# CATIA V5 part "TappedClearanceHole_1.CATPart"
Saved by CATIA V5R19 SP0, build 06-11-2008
Bounding box of the stored display mesh (mm): x -15.45 to 8.962, y -8.71 to 14.473, z -25.999 to 10.969
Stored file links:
  D:\D6\Data\SampleData\GeneralData\Catalog\Udfs\TappedClearanceHole_1.CATPart
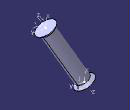
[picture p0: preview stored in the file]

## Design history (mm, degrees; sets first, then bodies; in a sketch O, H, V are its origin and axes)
AxisSystem1 "MainAxisSystem": origin (3.4402, -3.0557, 7.9698), X (-0.7522, -0.6549, 0.0736), Y (0.5427, -0.6789, -0.4946), Z (0.3738, -0.332, 0.866)
Intersect1 "Intersect": ToIntersect1 edge [ZX plane of AxisSystem1 | YZ plane of AxisSystem1], ToIntersect2 Plane2
Project1 "Project": Support Plane2, ToProject vertex [YZ plane of AxisSystem1 | ZX plane of AxisSystem1 | XY plane of AxisSystem1]
Body1 (main body)
  Point1: type OnPlane, Support xy-plane, Direction (1, 0, 0), H -42, V -75
  Point2: type OnPlane, Support xy-plane, Direction (1, 0, 0), H 109, V 95
  Line1: type PtPt, SecondPoint Point2, FirstPoint Point1
  Plane1 "InsertionDirection": type Angle, Angle 30, Direction Line1, RefPlane xy-plane
  Point3 "InsertionPoint": type OnPlane, Support Plane1, Direction (1, 0, 0), H 0, V 0
  Plane2 "LimitingSketchAxis": type Offset, Offset 20, RefPlane xy-plane, reversed
  Body2 "UDF_Body"
    Sketch1 "MainProfileSketch" on ZX plane of AxisSystem1, origin (3.4402, -3.0557, 7.9698), H (0.7522, 0.6549, -0.0736), V (0.3738, -0.332, 0.866)
      axis line L1 (0, 0) -> (0, -35.7608)
      point P2 (4.25, -34.0108)
      line L2 (4.25, -34.0108) -> (4.25, -1.75)
      line L3 (4.25, -1.75) -> (6, 0)
      point P3 (6, 0)
      line L4 (6, 0) -> (6, 0)
      line L5 (6, 0) -> (6, 0)
      line L6 (6, 0) -> (0, 0)
      construction line L7 (6, 0) -> (0, 0)
      reference projected line E1 through (0, 0) direction (-1, 0) from edge [XY plane of AxisSystem1 | ZX plane of AxisSystem1]
      reference projected line E2 through (0, 0) direction (-1, 0) from edge [XY plane of AxisSystem1 | ZX plane of AxisSystem1]
      reference projected line E3 through (0, 0) direction (-1, 0) from edge [XY plane of AxisSystem1 | ZX plane of AxisSystem1]
      reference projected line E4 through (0, 0) direction (0, 1) from edge [ZX plane of AxisSystem1 | YZ plane of AxisSystem1]
      line L8 (4.25, -34.0108) -> (6, -35.7608)
      point P6 (6, -35.7608)
      line L9 (6, -35.7608) -> (0, -35.7608)
      point P8 (-6, -35.7608)
      point P9 (-4.25, -34.0108)
      construction line L10 (-4.25, -34.0108) -> (-6, -35.7608)
      point P10 (4.25, -1.75)
      point P11 (-6, 0)
      point P12 (-4.25, -1.75)
      construction line L11 (-4.25, -1.75) -> (-6, 0)
      angle L3 L11 = 90
      "Radius" L1 L2 = 4.25 {= Body2.DK / 2}
      distance E1 L9 = 35.7608 {= Body2.Offset + (Sketch1.length(L9) * (Body2.Offset / Body2.Offset ))}
      length L7 = 6 {= sqrt((Body2.AS_H * Body2.AS_H ) + ((Groove1.top_width / 2 + Groove1.AS_ZR ) * (Groove1.top_width / 2 + Groove1.AS_ZR )))}
      angle L7 L4 = 0 {= atan(Body2.AS_H / (Groove1.top_width / 2 + Groove1.AS_ZR ))}
      angle L8 L10 = 90
      length L9 = 6 (reference)
      "Radius" P3 L1 = 6 {= Body2.DF1 / 2}
      "Radius" P6 L1 = 6 {= Body2.DF2 / 2}
      coincidence: E2 L4, L1 E4
      perpendicularity: L1 L6, E3 L5
      symmetry: P6 P8 L1, P2 P9 L1, L8 L10 L1, P3 P11 L1, P10 P12 L1, L3 L11 L1
    Groove1 "MainGroove": profile Sketch1, axis Sketch1.L1, angle 360
    Thread1 "Tap": diameter 10, depth 30, pitch 1.5, on face of Groove1 from Sketch1.L2, from {plane type Normal, Curve edge [ZX plane of AxisSystem1 | YZ plane of AxisSystem1], RefPoint vertex [YZ plane of AxisSystem1 | ZX plane of AxisSystem1 | XY plane of AxisSystem1]}
    Point4 "LimitingAxisSystemOrigin": type OnCurve, Support edge [ZX plane of AxisSystem1 | YZ plane of AxisSystem1], Length 3.4641 {= (Sketch1.length(L9)) * (Body2.Offset / Body2.Offset)}, RefPoint Intersect1
    AxisSystem2 "LimitingAxisSystem": origin (-9.9281, 8.8185, -23), X (-0.7522, -0.6549, 0.0736), Y (0.5427, -0.6789, -0.4946), Z (-0.3738, 0.332, -0.866)
  Assemble1 "UDF_Assemble": tool Body2
Body3 "UDF_Body"
  AxisSystem3 "MainAxisSystem": origin (3.4402, -3.0557, 7.9698), X (-0.7522, -0.6549, 0.0736), Y (0.5427, -0.6789, -0.4946), Z (0.3738, -0.332, 0.866)
  Project2 "Project": Support Plane2, ToProject vertex [YZ plane of AxisSystem3 | ZX plane of AxisSystem3 | XY plane of AxisSystem3]
  Intersect2 "Intersect": ToIntersect1 edge [ZX plane of AxisSystem3 | YZ plane of AxisSystem3], ToIntersect2 Plane2
  Sketch2 "MainProfileSketch" on ZX plane of AxisSystem3, origin (3.4402, -3.0557, 7.9698), H (0.7522, 0.6549, -0.0736), V (0.3738, -0.332, 0.866)
    axis line L1 (0, 0) -> (0, -35.7608)
    point P2 (4.25, -34.0108)
    line L2 (4.25, -34.0108) -> (4.25, -1.75)
    line L3 (4.25, -1.75) -> (6, 0)
    point P3 (6, 0)
    line L4 (6, 0) -> (6, 0)
    line L5 (6, 0) -> (6, 0)
    line L6 (6, 0) -> (0, 0)
    construction line L7 (6, 0) -> (0, 0)
    reference projected line E1 through (0, 0) direction (-1, 0) from edge [XY plane of AxisSystem3 | ZX plane of AxisSystem3]
    reference projected line E2 through (0, 0) direction (-1, 0) from edge [XY plane of AxisSystem3 | ZX plane of AxisSystem3]
    reference projected line E3 through (0, 0) direction (-1, 0) from edge [XY plane of AxisSystem3 | ZX plane of AxisSystem3]
    reference projected line E4 through (0, 0) direction (0, 1) from edge [ZX plane of AxisSystem3 | YZ plane of AxisSystem3]
    line L8 (4.25, -34.0108) -> (6, -35.7608)
    point P6 (6, -35.7608)
    line L9 (6, -35.7608) -> (0, -35.7608)
    point P8 (-6, -35.7608)
    point P9 (-4.25, -34.0108)
    construction line L10 (-4.25, -34.0108) -> (-6, -35.7608)
    point P10 (4.25, -1.75)
    point P11 (-6, 0)
    point P12 (-4.25, -1.75)
    construction line L11 (-4.25, -1.75) -> (-6, 0)
    angle L3 L11 = 90
    "UIHidden_zDK" L1 L2 = 4.25 {= Body3.DK / 2}
    distance E1 L9 = 35.7608 {= Body3.Offset + (Sketch2.length(L9) * (Body3.Offset / Body3.Offset ))}
    length L7 = 6 {= sqrt((Body3.AS_H * Body3.AS_H ) + ((Groove2.top_width / 2 + Groove2.AS_ZR ) * (Groove2.top_width / 2 + Groove2.AS_ZR )))}
    angle L7 L4 = 0 {= atan(Body3.AS_H / (Groove2.top_width / 2 + Groove2.AS_ZR ))}
    angle L8 L10 = 90
    length L9 = 6 (reference)
    "UIHidden_zDF1" P3 L1 = 6 {= Body3.DF1 / 2}
    "UIHidden_zDF2" P6 L1 = 6 {= Body3.DF2 / 2}
    coincidence: E2 L4, L1 E4
    perpendicularity: L1 L6, E3 L5
    symmetry: P6 P8 L1, P2 P9 L1, L8 L10 L1, P3 P11 L1, P10 P12 L1, L3 L11 L1
  Groove2 "MainGroove": profile Sketch2, axis Sketch2.L1, angle 360
  Thread2 "Tap": diameter 10, depth 30, pitch 1.5, on face of Groove2 from Sketch2.L2, from {plane type Normal, Curve edge [ZX plane of AxisSystem3 | YZ plane of AxisSystem3], RefPoint vertex [YZ plane of AxisSystem3 | ZX plane of AxisSystem3 | XY plane of AxisSystem3]}
  Point5 "LimitingAxisSystemOrigin": type OnCurve, Support edge [ZX plane of AxisSystem3 | YZ plane of AxisSystem3], Length 3.4641 {= (Sketch2.length(L9)) * (Body3.Offset / Body3.Offset)}, RefPoint Intersect2
  AxisSystem4 "LimitingAxisSystem": origin (-9.9281, 8.8185, -23), X (-0.7522, -0.6549, 0.0736), Y (0.5427, -0.6789, -0.4946), Z (-0.3738, 0.332, -0.866)
Relations
  rule:
  Body2.W1 = Sketch1.angle(L3 L11)
  Body2.W2 = Sketch1.angle(L8 L10)
  rule "AS_ZR":
    /*Rule created by AKNOPP 03.08.2006*/
    Groove1.AS_ZR = Body2.AS_D - (2 * Sketch1.Radius(P3 L1))
    if (Body2.AS_D == 0mm)
    {
    	Groove1.AS_ZR = 0mm
    }
    else
    {
    	Groove1.AS_ZR = (Body2.AS_D / 2) - Sketch1.Radius(P3 L1)
    }
  Groove1.top_width = Body2.DF1
  Body2.LK = Sketch1.distance(E1 L9)
  Body2.DG = Thread1.Diameter
  Body2.TG = Thread1.Depth
  Body2.GB = Thread1.ThreadDescription
  Body2.P = Thread1.Pitch
  Body3.W1 = Sketch2.angle(L3 L11)
  Body3.W2 = Sketch2.angle(L8 L10)
  Groove2.top_width = Body3.DF1
  Body3.LK = Sketch2.distance(E1 L9)
  rule "AS_ZR":
    /*Rule created by AKNOPP 03.08.2006*/
    Groove2.AS_ZR = Body3.AS_D - (2 * Sketch2.UIHidden_zDF1(P3 L1))
    if (Body3.AS_D == 0mm)
    {
    	Groove2.AS_ZR = 0mm
    }
    else
    {
    	Groove2.AS_ZR = (Body3.AS_D / 2) - Sketch2.UIHidden_zDF1(P3 L1)
    }
  Body3.DG = Thread2.DG
  Body3.TG = Thread2.TG
  Body3.GB = Thread2.GB
  Body3.P = Thread2.P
